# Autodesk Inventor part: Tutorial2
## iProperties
Shininess: 64.0
Length Units: 11269
Angle Units: 11279
Time Units: 11290
Mass Units: 11283
Length Display Precision: 3
Angle Display Precision: 2
Compacted: True
Part Number: Tutorial2
Document SubType Name: Modeling
Created: 2002-12
Designer: deepak
Density: 0.0
Volumn: 0.0
Area: 0.0
PropertySet Name: Model Information
Control State: 0
Master: False
Checked Out: False
Author: deepak
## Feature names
1. Revolution2
